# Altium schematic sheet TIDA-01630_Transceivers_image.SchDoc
size 431 x 279 mm; Date: Not shown in title block; ApprovedBy: Not shown in title block; CheckedBy: Not shown in title block; Author: Not shown in title block; CompanyName: Not shown in title block; Engineer: Not shown in title block; Organization: Not shown in title block; Address1: Not shown in title block; Address2: Not shown in title block; Address3: Not shown in title block; Address4: Not shown in title block; DocumentNumber: 1; Revision: Use project parameter SCH_Rev; SheetNumber: 2; SheetTotal: 3; PageSetup: Record=PageOptions¦CenterHorizontal=True¦CenterVertical=True¦PrintScale=0.91¦XCorrection=1.00¦YCorrection=1.00¦PrintKind=0¦BorderSize=5000000¦LeftOffset=0¦BottomOffset=0¦Orientation=2¦PaperLength=1000¦PaperWidth=1000¦Scale=100¦PaperSource=15¦PrintQuality=-3¦MediaType=1¦DitherType=10¦PrintScaleMode=1¦PaperKind=A4¦PaperIndex=9
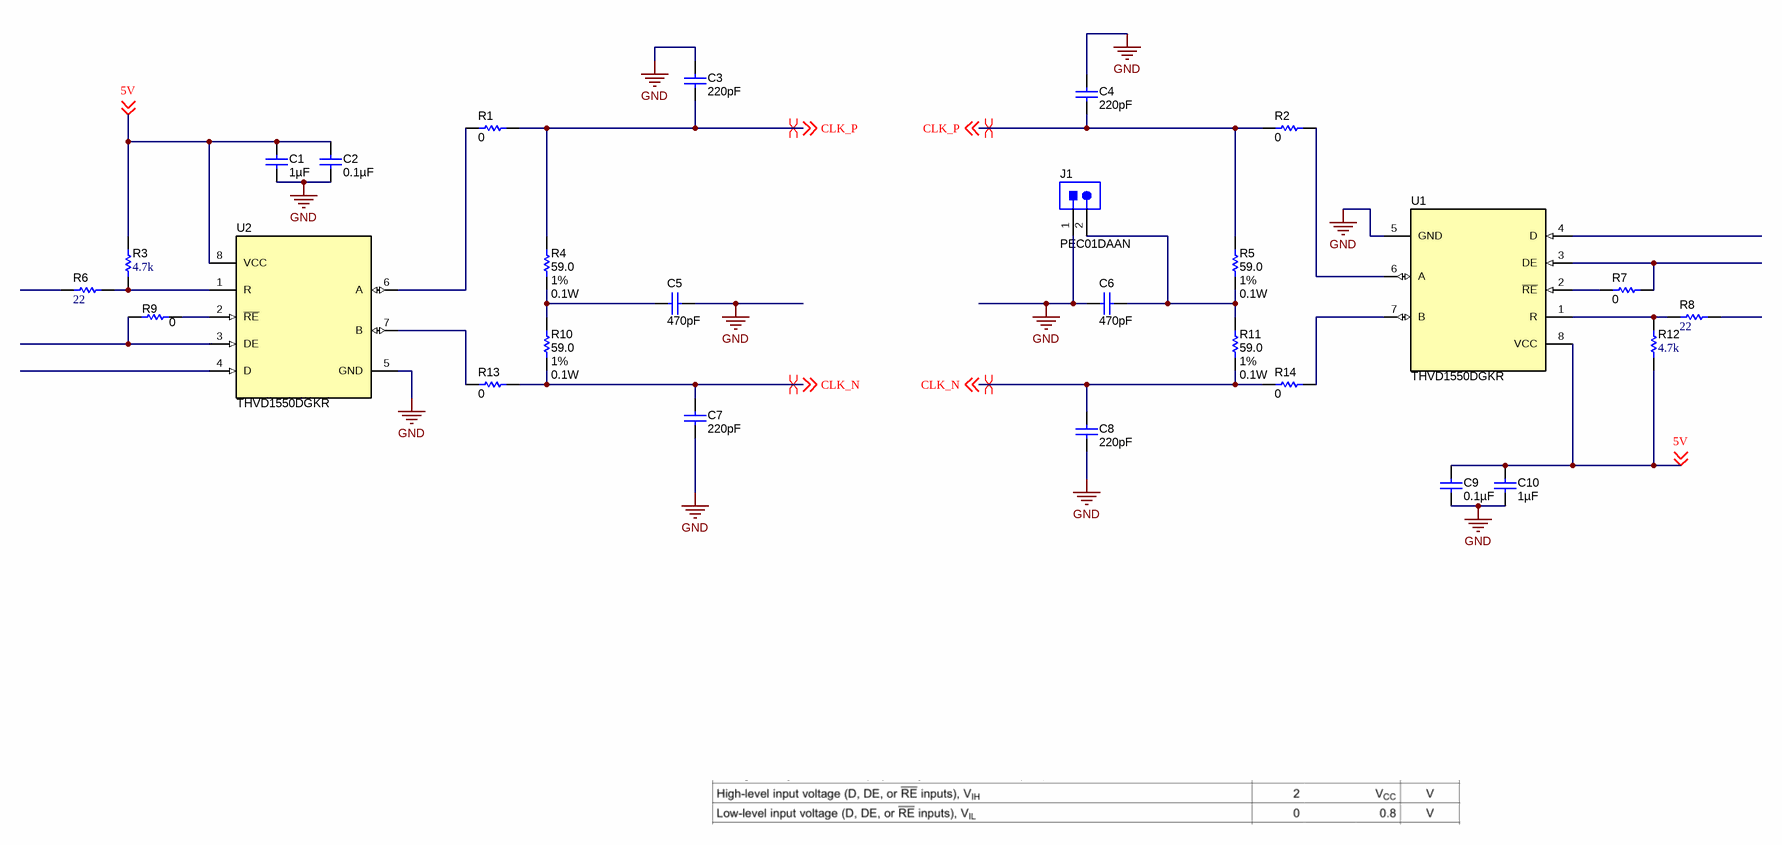
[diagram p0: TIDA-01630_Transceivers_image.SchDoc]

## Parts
C1  ValueDisplayed: 1µF  [0402S]  (hidden comment: GRM155R61A105KE15D)
C2  ValueDisplayed: 0.1µF  [0402S]  (hidden comment: 885012205037)
C3  ValueDisplayed: 220pF  [0603S]  (hidden comment: 06035A221FAT2A)
C4  ValueDisplayed: 220pF  [0603S]  (hidden comment: 06035A221FAT2A)
C5  ValueDisplayed: 470pF  [0603S]  (hidden comment: 885012206081)
C6  ValueDisplayed: 470pF  [0603S]  (hidden comment: 885012206081)
C7  ValueDisplayed: 220pF  [0603S]  (hidden comment: 06035A221FAT2A)
C8  ValueDisplayed: 220pF  [0603S]  (hidden comment: 06035A221FAT2A)
C9  ValueDisplayed: 0.1µF  [0402S]  (hidden comment: 885012205037)
C10  ValueDisplayed: 1µF  [0402S]  (hidden comment: GRM155R61A105KE15D)
J1  PEC01DAAN  [Sullins_PxC01DAAN]
R1  ValueDisplayed: 0  [0603S]  (hidden comment: CRCW06030000Z0EA)
R2  ValueDisplayed: 0  [0603S]  (hidden comment: CRCW06030000Z0EA)
R3  ValueDisplayed: 4.7k  [0402S]  (hidden comment: CRCW04024K70JNED)
R4  ValueDisplayed: 59.0  Value1: 1%  Value2: 0.1W  [0603S]  (hidden comment: RC0603FR-0759RL)
R5  ValueDisplayed: 59.0  Value1: 1%  Value2: 0.1W  [0603S]  (hidden comment: RC0603FR-0759RL)
R6  ValueDisplayed: 22  [0402S]  (hidden comment: CRCW040222R0JNED)
R7  ValueDisplayed: 0  [0402S]  (hidden comment: CRCW04020000Z0ED)
R8  ValueDisplayed: 22  [0402S]  (hidden comment: CRCW040222R0JNED)
R9  ValueDisplayed: 0  [0402S]  (hidden comment: CRCW04020000Z0ED)
R10  ValueDisplayed: 59.0  Value1: 1%  Value2: 0.1W  [0603S]  (hidden comment: RC0603FR-0759RL)
R11  ValueDisplayed: 59.0  Value1: 1%  Value2: 0.1W  [0603S]  (hidden comment: RC0603FR-0759RL)
R12  ValueDisplayed: 4.7k  [0402S]  (hidden comment: CRCW04024K70JNED)
R13  ValueDisplayed: 0  [0603S]  (hidden comment: CRCW06030000Z0EA)
R14  ValueDisplayed: 0  [0603S]  (hidden comment: CRCW06030000Z0EA)
U1  THVD1550DGKR  [DGK0008A_N]
U2  THVD1550DGKR  [DGK0008A_N]

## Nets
GND: C1.2 C2.2 C3.1 C4.1 C5.2 C6.2 C7.2 C8.1 C9.1 C10.1 J1.1 U1.5(GND) U2.5(GND)
5V: C1.1 C2.1 C9.2 C10.2 R3.2 R12.2 U1.8(VCC) U2.8(VCC) ; off-sheet 5V
CLK_N: C7.1 C8.2 R10.1 R11.2 R13.2 R14.2 ; off-sheet CLK_N
CLK_P: C3.2 C4.2 R1.2 R2.2 R4.2 R5.1 ; off-sheet CLK_P
NetC5_1: C5.1 R4.1 R10.2
NetC6_1: C6.1 J1.2 R5.2 R11.1
NetR1_1: R1.1 U2.6(A)
NetR2_1: R2.1 U1.6(A)
NetR3_1: R3.1 R6.2 U2.1(R)
NetR7_1: R7.1 U1.3(DE)
NetR7_2: R7.2 U1.2(~{RE})
NetR8_2: R8.2 R12.1 U1.1(R)
NetR9_1: R9.1 U2.3(DE)
NetR9_2: R9.2 U2.2(~{RE})
NetR13_1: R13.1 U2.7(B)
NetR14_1: R14.1 U1.7(B)

Not connected (* = marked no-connect by the designer): R6 1; R8 1; U1 4(D); U2 4(D)

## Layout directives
differential pair: CLK_N, CLK_P

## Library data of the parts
C1 C10 = GRM155R61A105KE15D: CAP, CERM, 1 µF, 10 V, +/- 10%, X5R, 0402; Manufacturer: MuRata; Polarized: N; CompType: Capacitor; Value: 1uF; U/M: EA; Cap_F: 0.000001; Tolerance_%: 10; Value1: Unknown; Value2: 10V; TaMin_C: -55; TaMax_C: 85; Cap_Case: 0402; SizeArea_mm2: 0.5; SizeAreaWB_mm2: 3; SizeX_mm: 1; SizeZ_mm: 0.6; AEC Category: Q200
C2 C9 = 885012205037: CAP, CERM, 0.1 µF, 16 V, +/- 10%, X7R, 0402; Manufacturer: Wurth Elektronik; Polarized: N; CompType: Capacitor; Value: 0.1uF; U/M: EA; Cap_F: 0.0000001; Tolerance_%: 10; Value1: Unknown; VDC_V: 16; Value2: 16V; TaMin_C: -55; TaMax_C: 125; Cap_Case: 0402; SizeArea_mm2: 0.5; SizeAreaWB_mm2: 3; SizeX_mm: 1; SizeZ_mm: 0.6; AEC Category: Q200
C3 C4 C7 C8 = 06035A221FAT2A: CAP, CERM, 220 pF, 50 V, +/- 1%, C0G/NP0, 0603; Manufacturer: AVX; Polarized: N; CompType: Capacitor; Value: 220pF; U/M: EA; Cap_F: 0.00000000022; Tolerance_%: 1; ESR_ohm: 0.083; Value1: 0.083 ohm; VDC_V: 50; Value2: 50V; TaMin_C: -55; TaMax_C: 125; Cap_Case: 0603; SizeArea_mm2: 1.28; SizeAreaWB_mm2: 4.68; SizeX_mm: 1.6; SizeY_mm: 0.8; AEC Category: Q200
C5 C6 = 885012206081: CAP, CERM, 470 pF, 50 V, +/- 10%, X7R, 0603; Manufacturer: Wurth Elektronik; Polarized: N; CompType: Capacitor; Value: 470pF; U/M: EA; Cap_F: 0.00000000047; Tolerance_%: 10; Value1: Unknown; VDC_V: 50; Value2: 50V; TaMin_C: -55; TaMax_C: 125; Cap_Case: 0603; SizeArea_mm2: 1.28; SizeAreaWB_mm2: 4.68; SizeX_mm: 1.6; SizeY_mm: 0.8; SizeZ_mm: 1; AEC Category: Q200
J1 = PEC01DAAN: Header, 2.54mm, 1x2, Tin, Black, TH; Manufacturer: Sullins Connector Solutions; SymbolCreator: a0412235; Pitch_mm: 2.54; Gender: Male; Shrouded: N; Row_Count: 2; Current_A: 3; Voltage_V: 1800; Cert_UL: Y
R1 R2 R13 R14 = CRCW06030000Z0EA: RES, 0, 5%, 0.1 W, 0603; Manufacturer: Vishay-Dale; CompType: Resistor; Value: 0; Value_Code: 0000; Tolerance_%: 5; Power_W: 0.1; Value2: 0.1W; VDC_V: 75; TempCo: 200 ppm/C; EIA_Code: E24; U/M: EA; SizeArea_mm2: 1.28; SizeX_mm: 1.6; SizeY_mm: 0.8; SizeZ_mm: 1; AEC Category: Q200
R3 R12 = CMP-0026938-4: RES, 4.7 k, 5%, 0.063 W, 0402; Manufacturer: Vishay-Dale; Power_W: 63mW; TempCo: 200 ppm/C; Value_Code: 4k70; U/M: EA; Value: 4.7k; EIA_Code: E24; SizeX_mm: 1; SizeY_mm: 0.5; SizeZ_mm: 0.6; Value2: 0.063W; CompType: Resistor; VDC_V: 50V; AEC Category: Q200
R4 R5 R10 R11 = RC0603FR-0759RL: RES, 59.0, 1%, 0.1 W, 0603; Manufacturer: Yageo America; CompType: Resistor; Value: 59.0; Res_ohm: 59; Value_Code: 59R0; Tolerance_%: 1; Power_W: 0.1; VDC_V: 150; TempCo: 200 ppm/C; SizeArea_mm2: 1.28; SizeX_mm: 1.6; SizeY_mm: 0.8; EIA_Code: E96; U/M: EA; AEC Category: Q200
R6 R8 = CMP-0026880-2: RES, 22, 5%, 0.063 W, 0402; Manufacturer: Vishay-Dale; Power_W: 63mW; TempCo: 200 ppm/C; Value_Code: 22R0; U/M: EA; Value: 22; EIA_Code: E24; SizeX_mm: 1; SizeY_mm: 0.5; SizeZ_mm: 0.6; Value2: 0.063W; CompType: Resistor; VDC_V: 50V; AEC Category: Q200
R7 R9 = CRCW04020000Z0ED: RES, 0, 5%, 0.063 W, 0402; Manufacturer: Vishay-Dale; CompType: Resistor; Value: 0; Value_Code: 0000; Tolerance_%: 5; Power_W: 0.063; Value2: 0.063W; VDC_V: 50; TempCo: 200 ppm/C; SizeArea_mm2: 0.5; SizeX_mm: 1; SizeZ_mm: 0.6; EIA_Code: E24; U/M: EA; AEC Category: Q200
U1 U2 = CMP-0074780-2: 5-V RS-485 Transceivers With +/-16-kV IEC ESD Protection, DGK0008A (VSSOP-8); Manufacturer: Texas Instruments; SizeX_mm: 5.05; SizeY_mm: 3.1; CompType: IC; SizeZ_mm: 1.1; SizeArea_mm2: 15.655; SizeAreaWB_mm2: 35.955; U/M: EA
